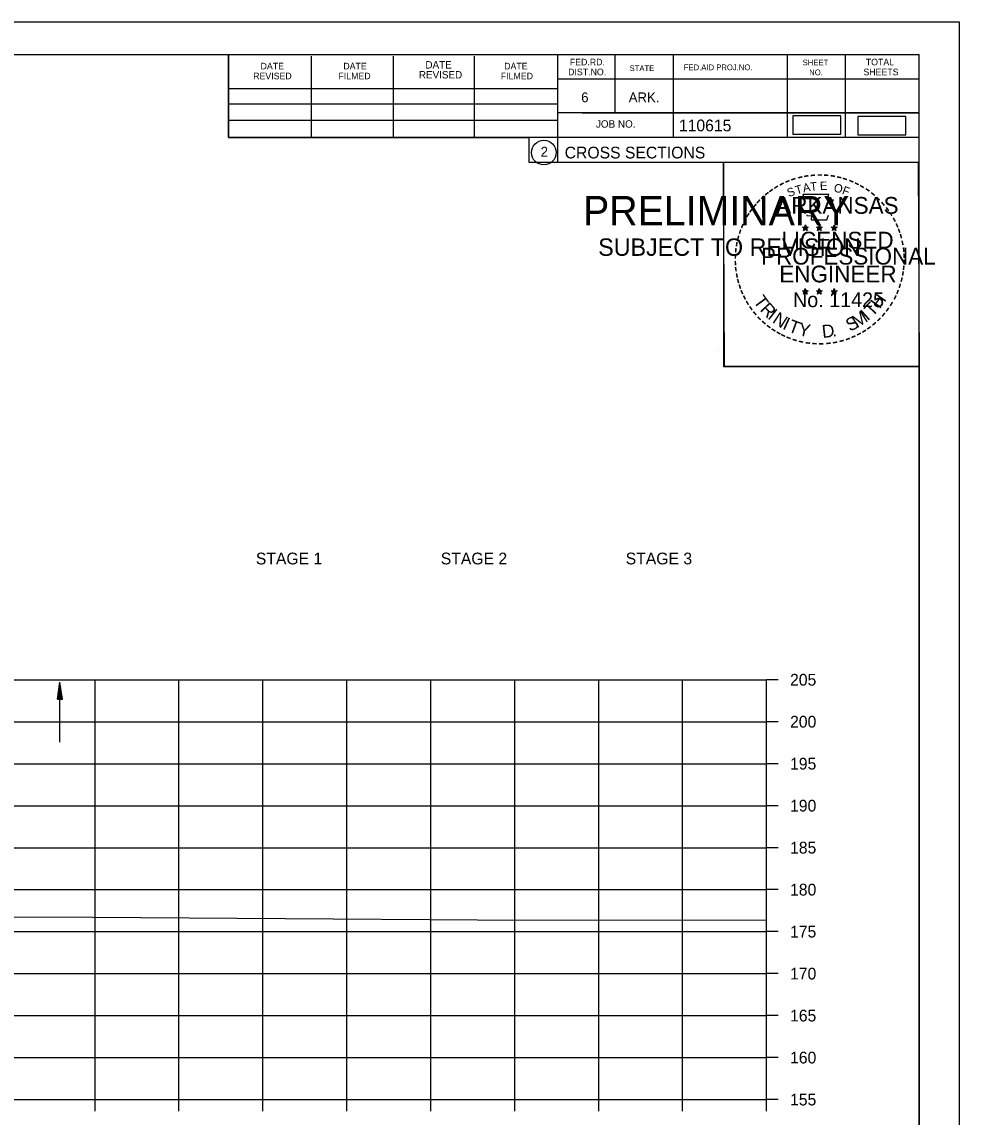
# Model space of a CAD drawing. Extents: x 1372132 to 1372465, y 380083 to 381790.
# Drawn here: x 1372353.3 to 1372464.9, y 380593.1 to 380723.5 of the extents above; entities that cross this region are included whole.
import ezdxf

# ---------------------------------------------------------------- set-up
doc = ezdxf.new("R2010")
doc.units = 0
for name, color, linetype in [('R_Axis', 7, 'Continuous'), ('R_Axis Annot', 7, 'Continuous'), ('R_Border', 7, 'Continuous'), ('R_Border PE', 7, 'Continuous'), ('R_Border Prem', 7, 'Continuous'), ('R_Dimension', 7, 'Continuous'), ('R_Draft', 7, 'Continuous'), ('R_Erosion', 7, 'Continuous'), ('R_Exist Surface', 7, 'Continuous'), ('R_Grid', 7, 'Continuous'), ('R_No Plot', 7, 'Continuous')]:
    doc.layers.add(name, color=color, linetype=linetype)

msp = doc.modelspace()

# ---------------------------------------------------------------- linework, layer by layer
at = {"layer": 'R_Axis'}
for p, q in [((1372442.01, 380595.15), (1372442.01, 380645.15)), ((1372443.41, 380645.15), (1372442.01, 380645.15)), ((1372443.41, 380640.15), (1372442.01, 380640.15)), ((1372443.41, 380635.15), (1372442.01, 380635.15)), ((1372443.41, 380630.15), (1372442.01, 380630.15)), ((1372443.41, 380625.15), (1372442.01, 380625.15)), ((1372443.41, 380620.15), (1372442.01, 380620.15)), ((1372443.41, 380615.15), (1372442.01, 380615.15)), ((1372443.41, 380610.15), (1372442.01, 380610.15)), ((1372443.41, 380605.15), (1372442.01, 380605.15)), ((1372443.41, 380600.15), (1372442.01, 380600.15)), ((1372162.01, 380595.15), (1372442.01, 380595.15)), ((1372362.01, 380593.75), (1372362.01, 380595.15)), ((1372372.01, 380593.75), (1372372.01, 380595.15)), ((1372382.01, 380593.75), (1372382.01, 380595.15)), ((1372392.01, 380593.75), (1372392.01, 380595.15)), ((1372402.01, 380593.75), (1372402.01, 380595.15)), ((1372412.01, 380593.75), (1372412.01, 380595.15)), ((1372422.01, 380593.75), (1372422.01, 380595.15)), ((1372432.01, 380593.75), (1372432.01, 380595.15)), ((1372442.01, 380593.75), (1372442.01, 380595.15)), ((1372443.41, 380595.15), (1372442.01, 380595.15))]:
    msp.add_line(p, q, dxfattribs=at)
at = {"layer": 'R_Border'}
for p, q in [((1372144.01, 380719.61), (1372460.19, 380719.61)), ((1372377.93, 380709.73), (1372377.93, 380719.61)), ((1372387.79, 380709.73), (1372387.79, 380719.41)), ((1372397.55, 380709.73), (1372397.55, 380719.41)), ((1372407.23, 380709.73), (1372407.23, 380719.41)), ((1372417.09, 380719.61), (1372417.09, 380706.81)), ((1372423.93, 380719.61), (1372423.93, 380712.67)), ((1372430.87, 380719.61), (1372430.87, 380709.73)), ((1372444.45, 380719.61), (1372444.45, 380709.73)), ((1372451.39, 380719.61), (1372451.39, 380709.73)), ((1372460.19, 380514.15), (1372460.19, 380719.61)), ((1372460.19, 380716.67), (1372417.09, 380716.67)), ((1372460.19, 380716.69), (1372460.19, 380716.69)), ((1372377.93, 380715.59), (1372417.09, 380715.59)), ((1372377.93, 380713.73), (1372417.09, 380713.73)), ((1372460.19, 380712.67), (1372417.09, 380712.67)), ((1372420.05, 380712.67), (1372460.19, 380712.67)), ((1372377.93, 380709.73), (1372377.93, 380711.79)), ((1372377.93, 380711.79), (1372417.09, 380711.79)), ((1372460.19, 380709.73), (1372377.93, 380709.73)), ((1372417.09, 380706.81), (1372460.19, 380706.81))]:
    msp.add_line(p, q, dxfattribs=at)
msp.add_circle((1372415.48, 380707.94), 1.47, dxfattribs=at)
at = {"layer": 'R_Border PE'}
for p, q in [((1372446.28, 380699.06), (1372446.63, 380698.95)), ((1372446.28, 380699.06), (1372446.53, 380699.02)), ((1372446.28, 380699.06), (1372446.52, 380698.94)), ((1372446.41, 380698.66), (1372446.63, 380698.95)), ((1372446.41, 380698.66), (1372446.54, 380698.9)), ((1372446.41, 380698.66), (1372446.63, 380698.87)), ((1372446.63, 380699.32), (1372446.59, 380699.07)), ((1372446.63, 380698.95), (1372446.63, 380699.32)), ((1372446.63, 380699.32), (1372446.68, 380699.07)), ((1372446.98, 380699.06), (1372446.63, 380698.95)), ((1372446.84, 380698.66), (1372446.63, 380698.95)), ((1372446.84, 380698.66), (1372446.63, 380698.87)), ((1372446.98, 380699.06), (1372446.69, 380699.02)), ((1372446.84, 380698.66), (1372446.7, 380698.95)), ((1372446.98, 380699.06), (1372446.77, 380698.96)), ((1372447.95, 380699.06), (1372448.3, 380698.95)), ((1372447.95, 380699.06), (1372448.2, 380699.02)), ((1372447.95, 380699.06), (1372448.19, 380698.94)), ((1372448.08, 380698.66), (1372448.3, 380698.95)), ((1372448.08, 380698.66), (1372448.21, 380698.9)), ((1372448.08, 380698.66), (1372448.3, 380698.87)), ((1372448.3, 380699.32), (1372448.26, 380699.07)), ((1372448.3, 380698.95), (1372448.3, 380699.32)), ((1372448.3, 380699.32), (1372448.35, 380699.07)), ((1372448.65, 380699.06), (1372448.3, 380698.95)), ((1372448.51, 380698.66), (1372448.3, 380698.95)), ((1372448.51, 380698.66), (1372448.3, 380698.87)), ((1372448.65, 380699.06), (1372448.36, 380699.02)), ((1372448.51, 380698.66), (1372448.37, 380698.95)), ((1372448.65, 380699.06), (1372448.44, 380698.96)), ((1372449.71, 380699.05), (1372450.06, 380698.94)), ((1372449.71, 380699.05), (1372449.97, 380699.01)), ((1372449.71, 380699.05), (1372449.95, 380698.93)), ((1372449.85, 380698.64), (1372450.06, 380698.94)), ((1372449.85, 380698.64), (1372449.97, 380698.89)), ((1372450.06, 380699.31), (1372450.02, 380699.05)), ((1372450.06, 380698.94), (1372450.06, 380699.31)), ((1372450.06, 380699.31), (1372450.11, 380699.06)), ((1372450.41, 380699.05), (1372450.06, 380698.94)), ((1372450.28, 380698.64), (1372450.06, 380698.94)), ((1372450.41, 380699.05), (1372450.12, 380699)), ((1372450.28, 380698.64), (1372450.14, 380698.94)), ((1372450.41, 380699.05), (1372450.21, 380698.95)), ((1372449.85, 380698.64), (1372450.06, 380698.86)), ((1372450.28, 380698.64), (1372450.06, 380698.86)), ((1372446.28, 380691.49), (1372446.62, 380691.38)), ((1372446.28, 380691.49), (1372446.53, 380691.45)), ((1372446.28, 380691.49), (1372446.51, 380691.37)), ((1372446.41, 380691.08), (1372446.62, 380691.38)), ((1372446.41, 380691.08), (1372446.53, 380691.33)), ((1372446.41, 380691.08), (1372446.62, 380691.3)), ((1372446.62, 380691.75), (1372446.58, 380691.49)), ((1372446.62, 380691.38), (1372446.62, 380691.75)), ((1372446.62, 380691.75), (1372446.67, 380691.5)), ((1372446.97, 380691.49), (1372446.62, 380691.38)), ((1372446.84, 380691.08), (1372446.62, 380691.38)), ((1372446.84, 380691.08), (1372446.62, 380691.3)), ((1372446.97, 380691.49), (1372446.69, 380691.44)), ((1372446.84, 380691.08), (1372446.7, 380691.37)), ((1372446.97, 380691.49), (1372446.77, 380691.39)), ((1372447.94, 380691.49), (1372448.29, 380691.38)), ((1372447.94, 380691.49), (1372448.2, 380691.45)), ((1372447.94, 380691.49), (1372448.18, 380691.37)), ((1372448.08, 380691.08), (1372448.29, 380691.38)), ((1372448.08, 380691.08), (1372448.2, 380691.33)), ((1372448.08, 380691.08), (1372448.29, 380691.3)), ((1372448.29, 380691.75), (1372448.25, 380691.49)), ((1372448.29, 380691.38), (1372448.29, 380691.75)), ((1372448.29, 380691.75), (1372448.34, 380691.5)), ((1372448.64, 380691.49), (1372448.29, 380691.38)), ((1372448.51, 380691.08), (1372448.29, 380691.38)), ((1372448.51, 380691.08), (1372448.29, 380691.3)), ((1372448.64, 380691.49), (1372448.35, 380691.44)), ((1372448.51, 380691.08), (1372448.37, 380691.37)), ((1372448.64, 380691.49), (1372448.44, 380691.39)), ((1372449.71, 380691.48), (1372450.06, 380691.37)), ((1372449.71, 380691.48), (1372449.96, 380691.44)), ((1372449.71, 380691.48), (1372449.95, 380691.36)), ((1372449.84, 380691.07), (1372450.06, 380691.37)), ((1372449.84, 380691.07), (1372449.97, 380691.32)), ((1372449.84, 380691.07), (1372450.06, 380691.29)), ((1372450.06, 380691.74), (1372450.02, 380691.48)), ((1372450.06, 380691.37), (1372450.06, 380691.74)), ((1372450.06, 380691.74), (1372450.11, 380691.49)), ((1372450.41, 380691.48), (1372450.06, 380691.37)), ((1372450.27, 380691.07), (1372450.06, 380691.37)), ((1372450.27, 380691.07), (1372450.06, 380691.29)), ((1372450.41, 380691.48), (1372450.12, 380691.43)), ((1372450.27, 380691.07), (1372450.14, 380691.36)), ((1372450.41, 380691.48), (1372450.2, 380691.38))]:
    msp.add_line(p, q, dxfattribs=at)
for points in [[(1372446.32, 380702.94), (1372446.59, 380702.12)], [(1372449.83, 380702.02), (1372449.97, 380702.3), (1372449.29, 380702.28), (1372449.44, 380702.94), (1372446.32, 380702.94)], [(1372446.81, 380700.52), (1372446.81, 380700.43), (1372447.38, 380700.41), (1372447.32, 380699.94), (1372449.19, 380699.94), (1372449.39, 380700.48)], [(1372446.63, 380699.32), (1372446.84, 380698.66), (1372446.28, 380699.06), (1372446.98, 380699.06), (1372446.41, 380698.66), (1372446.63, 380699.32)], [(1372448.3, 380699.32), (1372448.51, 380698.66), (1372447.95, 380699.06), (1372448.65, 380699.06), (1372448.08, 380698.66), (1372448.3, 380699.32)], [(1372450.06, 380699.31), (1372450.28, 380698.64), (1372449.71, 380699.05), (1372450.41, 380699.05), (1372449.85, 380698.64), (1372450.06, 380699.31)], [(1372446.62, 380691.75), (1372446.84, 380691.08), (1372446.28, 380691.49), (1372446.97, 380691.49), (1372446.41, 380691.08), (1372446.62, 380691.75)], [(1372448.29, 380691.75), (1372448.51, 380691.08), (1372447.94, 380691.49), (1372448.64, 380691.49), (1372448.08, 380691.08), (1372448.29, 380691.75)], [(1372450.06, 380691.74), (1372450.27, 380691.07), (1372449.71, 380691.48), (1372450.41, 380691.48), (1372449.84, 380691.07), (1372450.06, 380691.74)]]:
    msp.add_lwpolyline(points, dxfattribs=at)
for centre, radius in [((1372446.63, 380698.95), 0.172), ((1372446.63, 380698.95), 0.145), ((1372446.63, 380698.95), 0.116), ((1372446.63, 380698.95), 0.0991), ((1372446.63, 380698.95), 0.0747), ((1372446.63, 380698.95), 0.0495), ((1372446.63, 380698.95), 0.0296), ((1372448.3, 380698.95), 0.172), ((1372448.3, 380698.95), 0.145), ((1372448.3, 380698.95), 0.116), ((1372448.3, 380698.95), 0.0991), ((1372448.3, 380698.95), 0.0747), ((1372448.3, 380698.95), 0.0495), ((1372448.3, 380698.95), 0.0296), ((1372450.06, 380698.94), 0.172), ((1372450.06, 380698.94), 0.145), ((1372450.06, 380698.94), 0.116), ((1372450.06, 380698.94), 0.0991), ((1372450.06, 380698.94), 0.0747), ((1372450.06, 380698.94), 0.0495), ((1372450.06, 380698.94), 0.0296), ((1372446.62, 380691.38), 0.172), ((1372446.62, 380691.38), 0.145), ((1372446.62, 380691.38), 0.116), ((1372446.62, 380691.38), 0.0991), ((1372446.62, 380691.38), 0.0747), ((1372446.62, 380691.38), 0.0495), ((1372446.62, 380691.38), 0.0296), ((1372448.29, 380691.38), 0.172), ((1372448.29, 380691.38), 0.145), ((1372448.29, 380691.38), 0.116), ((1372448.29, 380691.38), 0.0991), ((1372448.29, 380691.38), 0.0747), ((1372448.29, 380691.38), 0.0495), ((1372448.29, 380691.38), 0.0296), ((1372450.06, 380691.37), 0.172), ((1372450.06, 380691.37), 0.145), ((1372450.06, 380691.37), 0.116), ((1372450.06, 380691.37), 0.0991), ((1372450.06, 380691.37), 0.0747), ((1372450.06, 380691.37), 0.0495), ((1372450.06, 380691.37), 0.0296)]:
    msp.add_circle(centre, radius, dxfattribs=at)
at = {"layer": 'R_Dimension'}
for p, q in [((1372357.52, 380642.85), (1372357.82, 380644.85)), ((1372357.52, 380642.85), (1372357.82, 380644.85)), ((1372357.57, 380642.85), (1372357.82, 380644.51)), ((1372357.57, 380642.85), (1372357.82, 380644.51)), ((1372357.62, 380642.85), (1372357.82, 380644.17)), ((1372357.62, 380642.85), (1372357.82, 380644.17)), ((1372358.12, 380642.85), (1372357.82, 380644.85)), ((1372358.12, 380642.85), (1372357.82, 380644.85)), ((1372358.07, 380642.85), (1372357.82, 380644.51)), ((1372358.07, 380642.85), (1372357.82, 380644.51)), ((1372358.02, 380642.85), (1372357.82, 380644.17)), ((1372358.02, 380642.85), (1372357.82, 380644.17)), ((1372357.52, 380642.85), (1372358.12, 380642.85)), ((1372357.52, 380642.85), (1372358.12, 380642.85)), ((1372357.67, 380642.85), (1372357.82, 380643.84)), ((1372357.67, 380642.85), (1372357.82, 380643.84)), ((1372357.72, 380642.85), (1372357.82, 380643.5)), ((1372357.72, 380642.85), (1372357.82, 380643.5)), ((1372357.77, 380642.85), (1372357.82, 380643.16)), ((1372357.77, 380642.85), (1372357.82, 380643.16)), ((1372357.97, 380642.85), (1372357.82, 380643.84)), ((1372357.97, 380642.85), (1372357.82, 380643.84)), ((1372357.92, 380642.85), (1372357.82, 380643.5)), ((1372357.92, 380642.85), (1372357.82, 380643.5)), ((1372357.87, 380642.85), (1372357.82, 380643.16)), ((1372357.87, 380642.85), (1372357.82, 380643.16))]:
    msp.add_line(p, q, dxfattribs=at)
at = {"layer": 'R_Draft'}
msp.add_line((1372357.82, 380637.71), (1372357.82, 380644.85), dxfattribs=at)
at = {"layer": 'R_Erosion'}
for points in [[(1372445.13, 380710.15), (1372450.85, 380710.15), (1372450.85, 380712.33), (1372445.13, 380712.33)], [(1372452.88, 380710.07), (1372458.59, 380710.07), (1372458.59, 380712.25), (1372452.88, 380712.25)]]:
    msp.add_lwpolyline(points, close=True, dxfattribs=at)
at = {"layer": 'R_Exist Surface'}
msp.add_lwpolyline([(1372351.82, 380616.91), (1372361.74, 380616.87), (1372407.58, 380616.54), (1372442.01, 380616.5)], dxfattribs=at)
at = {"layer": 'R_Grid'}
for p, q in [((1372162.01, 380645.15), (1372442.01, 380645.15)), ((1372362.01, 380595.15), (1372362.01, 380645.15)), ((1372372.01, 380595.15), (1372372.01, 380645.15)), ((1372382.01, 380595.15), (1372382.01, 380645.15)), ((1372392.01, 380595.15), (1372392.01, 380645.15)), ((1372402.01, 380595.15), (1372402.01, 380645.15)), ((1372412.01, 380595.15), (1372412.01, 380645.15)), ((1372422.01, 380595.15), (1372422.01, 380645.15)), ((1372432.01, 380595.15), (1372432.01, 380645.15)), ((1372442.01, 380595.15), (1372442.01, 380645.15)), ((1372162.01, 380640.15), (1372442.01, 380640.15)), ((1372162.01, 380635.15), (1372442.01, 380635.15)), ((1372162.01, 380630.15), (1372442.01, 380630.15)), ((1372162.01, 380625.15), (1372442.01, 380625.15)), ((1372162.01, 380620.15), (1372442.01, 380620.15)), ((1372162.01, 380615.15), (1372442.01, 380615.15)), ((1372162.01, 380610.15), (1372442.01, 380610.15)), ((1372162.01, 380605.15), (1372442.01, 380605.15)), ((1372162.01, 380600.15), (1372442.01, 380600.15)), ((1372162.01, 380595.15), (1372442.01, 380595.15))]:
    msp.add_line(p, q, dxfattribs=at)
at = {"layer": 'R_No Plot'}
for p, q in [((1372131.61, 380723.5), (1372464.95, 380723.5)), ((1372436.23, 380684.35), (1372436.23, 380684.35))]:
    msp.add_line(p, q, dxfattribs=at)
for points in [[(1372131.61, 380723.5), (1372464.95, 380723.5), (1372464.95, 380510.17), (1372131.61, 380510.17)], [(1372377.93, 380719.61), (1372377.93, 380709.73), (1372413.67, 380709.73), (1372413.67, 380706.81), (1372436.87, 380706.81), (1372436.87, 380682.48), (1372460.19, 380682.48), (1372460.19, 380514.15), (1372144.01, 380514.15), (1372144.01, 380719.61)], [(1372436.87, 380706.81), (1372460.07, 380706.81), (1372460.19, 380682.48), (1372436.99, 380682.48)]]:
    msp.add_lwpolyline(points, close=True, dxfattribs=at)

# ---------------------------------------------------------------- texts
at = {"layer": 'R_Axis Annot'}
for s, p in [('STAGE 1', (1372381.17, 380658.89)), ('STAGE 2', (1372403.2, 380658.89)), ('STAGE 3', (1372425.23, 380658.89)), ('205', (1372444.81, 380644.45)), ('200', (1372444.81, 380639.45)), ('195', (1372444.81, 380634.45)), ('190', (1372444.81, 380629.45)), ('185', (1372444.81, 380624.45)), ('180', (1372444.81, 380619.45)), ('175', (1372444.81, 380614.45)), ('170', (1372444.81, 380609.45)), ('165', (1372444.81, 380604.45)), ('160', (1372444.81, 380599.45)), ('155', (1372444.81, 380594.45))]:
    msp.add_text(s, height=1.4, dxfattribs=at).set_placement(p)
at = {"layer": 'R_Border'}
for s, height, p in [('DATE', 0.782, (1372381.73, 380717.85)), ('DATE', 0.782, (1372391.59, 380717.85)), ('DATE', 0.879, (1372401.37, 380717.95)), ('DATE', 0.782, (1372410.75, 380717.85)), ('FED.RD.', 0.782, (1372418.57, 380718.33)), ('FED.AID PROJ.NO.', 0.684, (1372432.15, 380717.75)), ('SHEET', 0.684, (1372446.31, 380718.33)), ('TOTAL', 0.782, (1372453.83, 380718.33)), ('REVISED', 0.782, (1372380.85, 380716.67)), ('FILMED', 0.782, (1372391.01, 380716.67)), ('REVISED', 0.879, (1372400.59, 380716.77)), ('FILMED', 0.782, (1372410.35, 380716.67)), ('DIST.NO.', 0.782, (1372418.37, 380717.15)), ('STATE', 0.684, (1372425.69, 380717.65)), ('NO.', 0.684, (1372447.09, 380717.15)), ('SHEETS', 0.782, (1372453.55, 380717.15)), ('6', 1.17, (1372419.93, 380713.93)), ('ARK.', 1.172, (1372425.59, 380713.93)), ('JOB NO.', 0.879, (1372421.69, 380710.91)), ('110615', 1.4, (1372431.57, 380710.47)), ('2', 1.17, (1372415.1, 380707.46)), ('CROSS SECTIONS', 1.4, (1372417.96, 380707.24))]:
    msp.add_text(s, height=height, rotation=360, dxfattribs=at).set_placement(p)
at = {"layer": 'R_Border PE'}
for s, height, rotation, p in [('-', 1.6, 28.7918, (1372443.8, 380703.48)), ('-', 1.6, 24.3072, (1372444.43, 380703.8)), ('-', 1.6, 19.1761, (1372445.07, 380704.07)), ('T', 1, 16.4036, (1372445.59, 380702.95)), ('-', 1.6, 13.6301, (1372445.82, 380704.31)), ('A', 1, 11.2132, (1372446.42, 380703.2)), ('-', 1.6, 10.2193, (1372446.5, 380704.47)), ('T', 1, 6.0228, (1372447.26, 380703.37)), ('-', 1.6, 5.8968, (1372447.23, 380704.58)), ('-', 1.6, 0.1862, (1372448, 380704.65)), ('E', 1, 0.8323, (1372448.37, 380703.48)), ('-', 1.6, 357.743, (1372448.72, 380704.64)), ('-', 1.6, 352.1617, (1372449.46, 380704.59)), ('O', 1, 350.4515, (1372449.97, 380703.27)), ('-', 1.6, 347.2049, (1372450.18, 380704.47)), ('-', 1.6, 342.3362, (1372450.82, 380704.32)), ('-', 1.6, 337.8551, (1372451.55, 380704.09)), ('-', 1.6, 334.1211, (1372452.18, 380703.82)), ('-', 1.6, 329.6409, (1372452.76, 380703.54)), ('-', 1.6, 42.9622, (1372441.72, 380701.92)), ('-', 1.6, 38.9507, (1372442.15, 380702.34)), ('-', 1.6, 36.2317, (1372442.63, 380702.72)), ('-', 1.6, 34.0636, (1372443.2, 380703.11)), ('S', 1, 21.594, (1372444.68, 380702.62)), ('F', 1, 340.0707, (1372450.93, 380703.04)), ('-', 1.6, 325.8627, (1372453.41, 380703.18)), ('-', 1.6, 320.5297, (1372454.02, 380702.75)), ('-', 1.6, 50.6142, (1372440.87, 380700.96)), ('-', 1.6, 48.423, (1372441.27, 380701.45)), ('ARKANSAS', 2, 360, (1372443.17, 380700.65)), ('-', 1.6, 315.5786, (1372454.62, 380702.26)), ('-', 1.6, 309.8797, (1372455.18, 380701.71)), ('-', 1.6, 58.0706, (1372440.13, 380699.87)), ('-', 1.6, 54.2325, (1372440.45, 380700.39)), ('-', 1.6, 306.6522, (1372455.71, 380701.11)), ('-', 1.4, 303.6753, (1372456.2, 380700.54)), ('-', 1.6, 299.6684, (1372456.51, 380699.94)), ('-', 1.6, 67.7743, (1372439.56, 380698.64)), ('-', 1.6, 62.8713, (1372439.82, 380699.25)), ('DWB', 0.01, 360, (1372446.62, 380698.95)), ('DWB', 0.01, 360, (1372448.29, 380698.95)), ('DWB', 0.01, 360, (1372450.05, 380698.94)), ('-', 1.6, 294.6628, (1372456.84, 380699.33)), ('-', 1.6, 290.5728, (1372457.1, 380698.75)), ('-', 1.6, 75.461, (1372439.14, 380697.3)), ('-', 1.6, 72.3945, (1372439.34, 380698.01)), ('LICENSED', 2, 360, (1372443.77, 380696.51)), ('-', 1.6, 285.1233, (1372457.33, 380698.17)), ('-', 1.6, 85.1863, (1372438.93, 380695.89)), ('-', 1.6, 81.2013, (1372439.01, 380696.58)), ('PROFESSIONAL', 2, 360, (1372441.35, 380694.6)), ('-', 1.6, 280.5493, (1372457.53, 380697.43)), ('-', 1.6, 276.5962, (1372457.69, 380696.66)), ('-', 1.6, 94.1959, (1372438.94, 380694.47)), ('-', 1.6, 89.0622, (1372438.91, 380695.19)), ('-', 1.6, 274.3301, (1372457.75, 380695.94)), ('-', 1.6, 269.9407, (1372457.79, 380695.3)), ('-', 1.6, 98.9479, (1372439.01, 380693.8)), ('ENGINEER', 2, 360, (1372443.53, 380692.48)), ('-', 1.6, 260.9953, (1372457.7, 380693.98)), ('-', 1.6, 263.5172, (1372457.77, 380694.64)), ('-', 1.6, 101.7149, (1372439.15, 380693.07)), ('-', 1.6, 105.4578, (1372439.31, 380692.47)), ('-', 1.6, 255.7626, (1372457.59, 380693.31)), ('-', 1.6, 109.0874, (1372439.53, 380691.84)), ('-', 1.6, 114.0643, (1372439.78, 380691.24)), ('T', 1.54, 306.0406, (1372440.38, 380690.22)), ('No. 11425', 1.757, 360, (1372445.16, 380689.53)), ('DWB', 0.01, 360, (1372446.61, 380691.38)), ('DWB', 0.01, 360, (1372448.28, 380691.38)), ('DWB', 0.01, 360, (1372450.05, 380691.37)), ('H', 1.54, 54.6088, (1372455.5, 380689.25)), ('-', 1.6, 247.8887, (1372457.18, 380691.91)), ('-', 1.6, 252.8681, (1372457.4, 380692.59)), ('-', 1.6, 115.7289, (1372440.09, 380690.63)), ('-', 1.6, 120.4471, (1372440.44, 380690.04)), ('R', 1.54, 314.005, (1372441.15, 380689.17)), ('T', 1.54, 46.6444, (1372454.61, 380688.31)), ('-', 1.6, 239.0712, (1372456.53, 380690.53)), ('-', 1.6, 244.6197, (1372456.92, 380691.28)), ('-', 1.6, 125.8934, (1372440.85, 380689.48)), ('-', 1.6, 130.7181, (1372441.31, 380688.93)), ('-', 1.6, 134.2238, (1372441.82, 380688.38)), ('I', 1.54, 321.9694, (1372442.05, 380688.24)), ('N', 1.54, 326.5002, (1372442.61, 380687.77)), ('M', 1.54, 32.6563, (1372452.77, 380686.99)), ('I', 1.54, 42.1136, (1372454.05, 380687.83)), ('-', 1.6, 231.2538, (1372455.69, 380689.31)), ('-', 1.6, 233.8452, (1372456.12, 380689.88)), ('-', 1.6, 138.9338, (1372442.35, 380687.92)), ('-', 1.6, 144.6463, (1372442.91, 380687.51)), ('I', 1.54, 335.3603, (1372443.82, 380686.98)), ('T', 1.54, 339.8912, (1372444.48, 380686.65)), ('Y', 1.54, 347.8556, (1372445.7, 380686.21)), ('D', 1.54, 6.3969, (1372448.69, 380685.85)), ('S', 1.54, 26.9312, (1372451.93, 380686.58)), ('-', 1.6, 215.7363, (1372454.14, 380687.77)), ('-', 1.6, 221.0851, (1372454.69, 380688.24)), ('-', 1.6, 225.7653, (1372455.21, 380688.75)), ('-', 1.6, 148.0898, (1372443.47, 380687.14)), ('-', 1.6, 151.5704, (1372444.05, 380686.82)), ('-', 1.6, 154.6002, (1372444.57, 380686.57)), ('-', 1.6, 158.5612, (1372445.19, 380686.32)), ('.', 1.54, 13.7642, (1372449.88, 380685.98)), ('-', 1.6, 200.7184, (1372451.81, 380686.44)), ('-', 1.6, 204.2516, (1372452.43, 380686.72)), ('-', 1.6, 207.3568, (1372453.05, 380687.04)), ('-', 1.6, 212.2491, (1372453.61, 380687.38)), ('-', 1.6, 162.7983, (1372445.88, 380686.1)), ('-', 1.6, 167.5555, (1372446.59, 380685.94)), ('-', 1.6, 173.1155, (1372447.37, 380685.83)), ('-', 1.6, 176.5183, (1372448.11, 380685.78)), ('-', 1.6, 181.5918, (1372448.86, 380685.79)), ('-', 1.6, 185.8167, (1372449.67, 380685.87)), ('-', 1.6, 191.2858, (1372450.4, 380686)), ('-', 1.6, 195.4743, (1372451.13, 380686.2))]:
    msp.add_text(s, height=height, rotation=rotation, dxfattribs=at).set_placement(p)
at = {"layer": 'R_Border Prem'}
for s, height, p in [('PRELIMINARY', 3.5, (1372420.15, 380699.27)), ('DWB', 0.01, (1372420.89, 380701.12)), ('SUBJECT TO REVISION', 2.0751, (1372421.95, 380695.64))]:
    msp.add_text(s, height=height, rotation=360, dxfattribs=at).set_placement(p)

doc.saveas('drawing.dxf')
